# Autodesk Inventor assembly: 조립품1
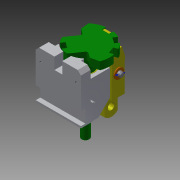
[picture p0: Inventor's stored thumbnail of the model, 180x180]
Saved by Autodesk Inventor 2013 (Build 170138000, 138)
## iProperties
Created: 2016-11
Part Number: 조립품1
Document SubType Name: Assembly
Designer: Administrator
Author: Administrator
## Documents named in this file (8)
- C:\Users\Administrator\Desktop\461107V1009\완성품.iam
- C:\Users\Administrator\Desktop\461107V1009\본체.ipt
- C:\Users\Administrator\Desktop\461107V1009\부시.ipt
- C:\Users\Administrator\Desktop\461107V1009\분할대.ipt
- C:\Users\Administrator\Desktop\461107V1009\분할축.ipt
- C:\Users\Administrator\Desktop\461107V1009\와셔.ipt
- C:\Users\Administrator\Desktop\461107V1009\원통형핀.ipt
- C:\Users\Administrator\Desktop\461107V1009\클레비스핀.ipt
